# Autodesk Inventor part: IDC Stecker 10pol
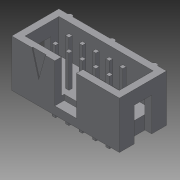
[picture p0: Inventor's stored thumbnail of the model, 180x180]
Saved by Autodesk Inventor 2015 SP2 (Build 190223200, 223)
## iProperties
Created: 2015-08
Part Number: IDC Stecker 10pol
Material: Allgemein
Document SubType Name: Modeling
Designer: ryll
Density: 1 g/cm^3
Appearance: Vorgabe
Author: ryll
Author: workeradm
Title: C-1761681-03-3
Organization: Tyco Electronics Corporation
Sending System: PRO/ENGINEER BY PARAMETRIC TECHNOLOGY CORPORATION, 2005450
Preprocessor: PRO/ENGINEER BY PARAMETRIC TECHNOLOGY CORPORATION, 2005450
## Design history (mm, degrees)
node "c-1761681-03-a-3d1"
node "Volumenkörper1"
node "Basis1"
